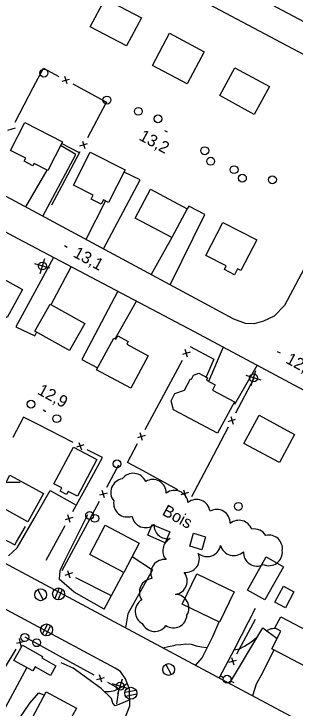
# Model space of a CAD drawing. Extents: x 219136 to 222520, y 5421589 to 5424530.
# Drawn here: x 220808.4 to 220879.7, y 5423742.7 to 5423918.8 of the extents above; entities that cross this region are included whole.
import ezdxf

# ---------------------------------------------------------------- set-up
doc = ezdxf.new("R2010")
doc.units = 0
for name, color, linetype in [('Level 19', 7, 'Continuous'), ('Level 2', 7, 'Continuous'), ('Level 21', 7, 'Continuous'), ('Level 3', 7, 'Continuous'), ('Level 31', 7, 'Continuous'), ('Level 36', 7, 'Continuous'), ('Level 37', 7, 'Continuous'), ('Level 44', 7, 'Continuous'), ('Level 61', 7, 'Continuous')]:
    doc.layers.add(name, color=color, linetype=linetype)

msp = doc.modelspace()

# ---------------------------------------------------------------- linework, layer by layer
at = {"layer": 'Level 19'}
for points in [[(220815.71, 5423867.5), (220824.08, 5423883.14), (220820.21, 5423885.48)], [(220816.77, 5423879.22), (220811.33, 5423869.85)], [(220831.13, 5423859.2), (220840.37, 5423876.71), (220836.32, 5423878.71)], [(220831.61, 5423871.39), (220826.62, 5423861.63)], [(220847.99, 5423850.13), (220856.79, 5423867.98), (220852.77, 5423870.05), (220852.29, 5423869.41)], [(220848.4, 5423862.1), (220843.18, 5423852.72)], [(220818.44, 5423857.04), (220808.89, 5423839.47), (220813.68, 5423837.13), (220814.16, 5423838.04)], [(220817.84, 5423845.07), (220822.89, 5423854.7)], [(220834.72, 5423848.47), (220825.61, 5423831.11), (220829.63, 5423829.05)], [(220834.08, 5423836.38), (220839.45, 5423845.98)], [(220861.48, 5423834.31), (220857.76, 5423825.6)], [(220870.07, 5423829.71), (220870.07, 5423829.7), (220864.33, 5423819.76)], [(220807.06, 5423781.33), (220809.21, 5423783.37), (220813.55, 5423790.78), (220817.55, 5423797.92), (220823.91, 5423794.35)], [(220827.05, 5423791.73), (220821.11, 5423779.89), (220820.05, 5423777.53), (220819.88, 5423775.43)], [(220838.39, 5423781.17), (220843.56, 5423777.78), (220837.27, 5423766.61), (220836.69, 5423763.04)], [(220831.25, 5423767.8), (220836.29, 5423777.13)], [(220869.61, 5423767.94), (220864.24, 5423757.54), (220860.43, 5423750.33)], [(220854.42, 5423753.54), (220856.1, 5423755.43), (220858.86, 5423760.84), (220860.44, 5423764.57)], [(220863.09, 5423748.9), (220871.52, 5423763.09), (220875.13, 5423760.38)], [(220874.34, 5423757.46), (220871.43, 5423751.64), (220869.79, 5423748.75), (220868.93, 5423745.78)], [(220837.77, 5423744.76), (220837.76, 5423744.76), (220835.39, 5423743.76), (220834.1, 5423743.26), (220833.5, 5423743.9), (220833.12, 5423745.1), (220830.54, 5423747.69), (220823.43, 5423752.81), (220820.34, 5423754.17)], [(220811.71, 5423752.96), (220805.01, 5423740.58), (220808.49, 5423738.12), (220812.45, 5423743.9), (220814.7, 5423746.55), (220816.11, 5423745.96)]]:
    msp.add_lwpolyline(points, dxfattribs=at)
at = {"layer": 'Level 2'}
for points in [[(220872.49, 5423762.36), (220873.63, 5423762.88), (220873.95, 5423762.92), (220874.72, 5423762.97)], [(220864.22, 5423757.5), (220865.64, 5423757.76), (220866.88, 5423758.4), (220868.19, 5423759.25), (220869.2, 5423760.02), (220870.18, 5423760.84)], [(220846.16, 5423757.97), (220847.63, 5423758.31), (220848.93, 5423758.58), (220849.45, 5423758.71), (220850.75, 5423758.86), (220852, 5423759.01), (220853.36, 5423758.89), (220854.6, 5423758.5), (220855.94, 5423758.26), (220857.44, 5423758.06)], [(220831.31, 5423746.92), (220832.64, 5423746.9), (220833.97, 5423747.16), (220835.21, 5423747.76), (220836.49, 5423748.52), (220837.08, 5423749.02)]]:
    msp.add_lwpolyline(points, dxfattribs=at)
at = {"layer": 'Level 21'}
for points in [[(220826.69, 5423937.93), (220900.24, 5423898.82), (220901.06, 5423896.99), (220901.36, 5423894.2), (220900.6, 5423891.33), (220898.93, 5423887.11), (220896.32, 5423881.44), (220893.83, 5423876.24), (220890.47, 5423870.14)], [(220995.49, 5423678.29), (220996.19, 5423681.93), (221004.73, 5423697.94), (221021.75, 5423729.83), (221039.74, 5423765.29), (221053.95, 5423791.88), (221056.68, 5423797.99), (221058, 5423802.9), (221058.22, 5423809.79), (221057.3, 5423814.77), (221055.3, 5423819.73), (221052.73, 5423823.47), (221048.19, 5423828.12), (221044.49, 5423830.59), (221027, 5423839.69), (220987.65, 5423860.46), (220947.14, 5423882.17), (220909.34, 5423902.28), (220864.28, 5423926.29)], [(220890.47, 5423870.14), (220876.98, 5423844.81), (220874.43, 5423842.18), (220871.7, 5423840.84), (220869.29, 5423840.24), (220867.08, 5423840.27), (220864.19, 5423841.41), (220808.77, 5423871.23), (220757.05, 5423898.78), (220743.22, 5423906.76), (220739.01, 5423909.89), (220736.41, 5423913.05), (220734.33, 5423917.05), (220733.8, 5423922.07)], [(220724.64, 5423919.94), (220726.19, 5423914.33), (220728.49, 5423909.82), (220732.21, 5423905.23), (220736.01, 5423901.71), (220742.64, 5423897.61), (220763.85, 5423886.35), (220809.37, 5423861.82), (220854.1, 5423838.27), (220902.48, 5423812.33), (220943.93, 5423790.02), (220983.67, 5423769), (221016, 5423751.84), (221018.21, 5423749.94), (221019.51, 5423747.38), (221019.63, 5423744.57), (221018.36, 5423740.94), (221004.35, 5423715.58), (220996.36, 5423700.59), (220991.52, 5423693.41), (220988.5, 5423688.97), (220985.79, 5423686.18), (220984.37, 5423685.17), (220983.05, 5423684.44)], [(220948.95, 5423703), (220904.47, 5423726.78), (220853.86, 5423753.84), (220802.2, 5423781.53), (220756.87, 5423805.98), (220752.54, 5423808.02), (220749.08, 5423809.42), (220742.93, 5423811.71), (220736.7, 5423813.64), (220729.21, 5423815.61), (220722.71, 5423817.16), (220715.9, 5423818.25), (220709.13, 5423819.02), (220700.46, 5423819.59), (220693.39, 5423819.74), (220687.57, 5423819.54), (220678.98, 5423818.61), (220672.46, 5423817.66), (220660.87, 5423814.84)], [(220837.82, 5423743.23), (220837.67, 5423747.47), (220836.68, 5423750.08), (220835.42, 5423751.94), (220834.1, 5423752.79), (220790.53, 5423776.18), (220757.42, 5423793.74), (220751.89, 5423796.6), (220745.6, 5423799.45), (220739.31, 5423801.83), (220731.18, 5423804.33), (220723.66, 5423806.27), (220711.25, 5423808.22), (220700.8, 5423809.13), (220692.45, 5423809.16), (220680.51, 5423808.54), (220669.68, 5423806.84), (220660.39, 5423804.75)], [(220831.25, 5423767.8), (220823.63, 5423772.14), (220819.88, 5423775.43)], [(220810.43, 5423694.93), (220812.84, 5423696.76), (220815.62, 5423700.25), (220820.54, 5423708.61), (220834.15, 5423733.92), (220837.82, 5423743.23)]]:
    msp.add_lwpolyline(points, dxfattribs=at)
at = {"layer": 'Level 3'}
for p, q in [((220846.58, 5423889.26), (220847.28, 5423888.88)), ((220821.23, 5423860.05), (220821.93, 5423859.67)), ((220875.19, 5423833.21), (220875.89, 5423832.83)), ((220815.82, 5423818.35), (220816.52, 5423817.97))]:
    msp.add_line(p, q, dxfattribs=at)
at = {"layer": 'Level 31'}
for points in [[(220836.98, 5423910.7), (220827.75, 5423915.56), (220831.54, 5423922.75), (220840.77, 5423917.88)], [(220852.31, 5423901.07), (220843.5, 5423905.77), (220847.85, 5423913.92), (220856.66, 5423909.23)], [(220869.33, 5423893.34), (220860.6, 5423898.1), (220864.45, 5423905.17), (220873.19, 5423900.41)], [(220811.17, 5423891.28), (220820.69, 5423886.41), (220816.96, 5423879.12), (220813.5, 5423880.89), (220813.21, 5423880.32), (220810.99, 5423881.46), (220811.4, 5423882.25), (220807.55, 5423884.22)], [(220827.75, 5423883.75), (220836.59, 5423879.24), (220832.39, 5423870.99), (220831.07, 5423871.66), (220830.5, 5423870.56), (220827.97, 5423871.85), (220828.47, 5423872.84), (220823.49, 5423875.38)], [(220843.03, 5423874.35), (220852.29, 5423869.41), (220848.4, 5423862.1), (220839.14, 5423867.04)], [(220861.37, 5423865.95), (220869.97, 5423861.53), (220865.96, 5423853.73), (220865.13, 5423854.16), (220864.34, 5423852.63), (220861.76, 5423853.96), (220862.24, 5423854.9), (220857.06, 5423857.56)], [(220806.65, 5423841.82), (220797.68, 5423846.8), (220801.59, 5423853.85), (220810.56, 5423848.88)], [(220822.5, 5423833.39), (220813.69, 5423838.3), (220817.55, 5423845.23), (220826.37, 5423840.32)], [(220838, 5423823.84), (220829.34, 5423828.51), (220833.69, 5423836.59), (220834.28, 5423836.27), (220834.74, 5423837.12), (220837.38, 5423835.69), (220837.02, 5423835.04), (220842.45, 5423832.11)], [(220860.05, 5423812.45), (220848.9, 5423818.39), (220848.23, 5423820.68), (220849.2, 5423822.5), (220851.66, 5423823.36), (220853.2, 5423826.26), (220853.39, 5423826.16), (220853.94, 5423827.2), (220855.26, 5423827.71), (220857.51, 5423826.51), (220857.19, 5423825.9), (220859.46, 5423824.7), (220858.76, 5423823.39), (220864.3, 5423820.44)], [(220875.71, 5423805), (220866.71, 5423809.86), (220870.55, 5423816.98), (220879.55, 5423812.13)], [(220818.55, 5423799.63), (220823.47, 5423808.92), (220829.42, 5423805.77), (220824.49, 5423796.46), (220822.18, 5423797.68), (220821.76, 5423796.89), (220820.13, 5423797.76), (220820.55, 5423798.57)], [(220811.96, 5423789.98), (220803.48, 5423794.58), (220807.38, 5423801.77), (220815.86, 5423797.18)], [(220831.54, 5423789.08), (220840.17, 5423784.57), (220836.29, 5423777.13), (220827.66, 5423781.64)], [(220843.46, 5423789.26), (220847.93, 5423787.38), (220846.79, 5423784.66), (220842.32, 5423786.53)], [(220852.98, 5423783.77), (220853.95, 5423787.08), (220856.98, 5423786.19), (220856.01, 5423782.88)], [(220867.61, 5423772.62), (220872.35, 5423781.07), (220876.79, 5423778.57), (220872.04, 5423770.13)], [(220860.53, 5423764.53), (220851.05, 5423769.09), (220854.74, 5423776.76), (220864.22, 5423772.2)], [(220874.59, 5423769.59), (220876.73, 5423773.61), (220879.4, 5423772.2), (220877.27, 5423768.17)], [(220876.07, 5423765.86), (220888.15, 5423759.54), (220884.32, 5423752.23), (220873.76, 5423757.76), (220876.11, 5423762.25), (220874.59, 5423763.04)], [(220813.19, 5423752.13), (220808.41, 5423754.8), (220810.55, 5423758.62), (220815.67, 5423755.75), (220815.5, 5423755.45), (220819.06, 5423753.45), (220817.66, 5423750.96), (220813.76, 5423753.15)], [(220811.64, 5423737.61), (220816.55, 5423746.78), (220824.24, 5423742.67), (220822.43, 5423739.29), (220822.85, 5423739.06), (220819.75, 5423733.27)]]:
    msp.add_lwpolyline(points, close=True, dxfattribs=at)
at = {"layer": 'Level 36'}
for p, q in [((220817.53, 5423854.29), (220813.72, 5423855.46)), ((220815.04, 5423852.97), (220816.21, 5423856.78)), ((220868.57, 5423824.56), (220869.74, 5423828.37)), ((220871.06, 5423825.88), (220867.25, 5423827.05)), ((220815.88, 5423770.11), (220814.48, 5423772.77)), ((220819.84, 5423773.17), (220818.74, 5423770.48)), ((220819.6, 5423770.15), (220820.7, 5423772.84)), ((220816.91, 5423764.01), (220815.58, 5423761.43)), ((220816.41, 5423761.03), (220817.74, 5423763.61)), ((220848.34, 5423751.14), (220846.94, 5423753.8)), ((220834.74, 5423746.32), (220835.91, 5423750.13)), ((220860.67, 5423750.96), (220861.55, 5423750.49)), ((220864.21, 5423749.1), (220863.31, 5423749.55)), ((220837.23, 5423747.64), (220833.42, 5423748.81)), ((220839.35, 5423747.19), (220836.51, 5423746.63)), ((220836.71, 5423745.73), (220839.55, 5423746.29))]:
    msp.add_line(p, q, dxfattribs=at)
for centre, radius in [((220816, 5423903.83), 1), ((220831.97, 5423896.98), 1), ((220839.94, 5423894.12), 1), ((220844.93, 5423892.22), 1), ((220856.79, 5423884.12), 1), ((220858.28, 5423881.46), 1), ((220864.23, 5423879.31), 1), ((220866.33, 5423877.16), 1), ((220873.95, 5423876.75), 1), ((220815.63, 5423854.88), 1), ((220869.16, 5423826.47), 1), ((220812.72, 5423819.82), 1), ((220819.25, 5423816.14), 1), ((220834.53, 5423804.68), 1), ((220865.31, 5423793.87), 1), ((220827.59, 5423791.57), 1), ((220828.9, 5423790.84), 1), ((220815.17, 5423771.45), 1.5), ((220819.71, 5423771.66), 1.52), ((220816.67, 5423762.52), 1.52), ((220811.17, 5423760.63), 1), ((220814.17, 5423759.28), 1), ((220847.63, 5423752.48), 1.5), ((220862.44, 5423750.02), 1), ((220835.33, 5423748.23), 1), ((220838.04, 5423746.46), 1.52)]:
    msp.add_circle(centre, radius, dxfattribs=at)
at = {"layer": 'Level 37'}
for p, q in [((220821.86, 5423901.08), (220821.29, 5423903)), ((220820.61, 5423901.75), (220822.53, 5423902.32)), ((220808.69, 5423889.86), (220806.78, 5423889.27)), ((220825.14, 5423885.34), (220827.05, 5423885.93)), ((220825.8, 5423886.59), (220826.39, 5423884.68)), ((220853.07, 5423832.98), (220851.15, 5423832.41)), ((220852.4, 5423831.74), (220851.83, 5423833.66)), ((220863.37, 5423816.69), (220863.96, 5423814.77)), ((220862.71, 5423815.43), (220864.62, 5423816.03)), ((220841.66, 5423811.87), (220839.74, 5423811.3)), ((220840.98, 5423810.63), (220840.41, 5423812.55)), ((220826.14, 5423809.48), (220824.24, 5423808.86)), ((220824.88, 5423810.12), (220825.5, 5423808.22)), ((220832, 5423797.26), (220830.08, 5423796.68)), ((220831.33, 5423796.01), (220830.75, 5423797.93)), ((220852.66, 5423797.39), (220850.74, 5423796.83)), ((220851.42, 5423798.07), (220851.98, 5423796.15)), ((220823.31, 5423791.06), (220821.38, 5423790.5)), ((220822.63, 5423789.82), (220822.07, 5423791.75)), ((220823.25, 5423776.98), (220821.34, 5423776.36)), ((220821.99, 5423777.62), (220822.6, 5423775.72)), ((220810.25, 5423758.36), (220809.78, 5423760.31)), ((220810.98, 5423759.57), (220809.04, 5423759.1)), ((220862.92, 5423754.32), (220864.84, 5423754.89)), ((220863.59, 5423755.56), (220864.16, 5423753.64)), ((220829.44, 5423749.93), (220831.36, 5423750.49)), ((220830.68, 5423749.25), (220830.12, 5423751.17))]:
    msp.add_line(p, q, dxfattribs=at)
for points in [[(220813.31, 5423900.19), (220815.89, 5423905.1), (220819.81, 5423902.99)], [(220823.33, 5423901.09), (220831.88, 5423896.48), (220831.74, 5423896.22)], [(220808.67, 5423891.34), (220813.31, 5423900.19)], [(220831.74, 5423896.22), (220827.04, 5423887.4)], [(220825.01, 5423883.59), (220820.46, 5423885.96)], [(220825.15, 5423883.87), (220820.45, 5423875.05)], [(220820.45, 5423875.05), (220817.91, 5423870.29)], [(220853.08, 5423834.42), (220859.1, 5423831.21), (220857.82, 5423828.3)], [(220846.4, 5423822.14), (220851.16, 5423830.94)], [(220857.82, 5423828.3), (220857.12, 5423826.72)], [(220869.25, 5423826.35), (220864.6, 5423817.5)], [(220841.65, 5423813.35), (220846.4, 5423822.14)], [(220814.52, 5423814.66), (220810.84, 5423816.55), (220808.1, 5423811.36)], [(220823.41, 5423810.09), (220814.52, 5423814.66)], [(220862.73, 5423813.96), (220858.08, 5423805.11)], [(220841.17, 5423802.86), (220837.16, 5423805.05), (220839.74, 5423809.83)], [(220828.11, 5423801.31), (220830.83, 5423806.27), (220826.97, 5423808.26)], [(220831.99, 5423798.73), (220835.04, 5423804.39)], [(220858.08, 5423805.11), (220853.43, 5423796.26)], [(220849.95, 5423798.07), (220841.17, 5423802.86)], [(220823.31, 5423792.54), (220828.11, 5423801.31)], [(220825.35, 5423786.41), (220830.09, 5423795.21)], [(220800.52, 5423788.31), (220808.59, 5423784.1), (220809.05, 5423784.88)], [(220809.05, 5423784.88), (220811.33, 5423788.77)], [(220816.58, 5423780.26), (220821.38, 5423789.03)], [(220820.6, 5423777.61), (220825.35, 5423786.41)], [(220832.99, 5423771.23), (220824.08, 5423775.77)], [(220869.6, 5423765.15), (220864.83, 5423756.36)], [(220811.12, 5423760.8), (220819.88, 5423755.99)], [(220803.76, 5423749.09), (220808.97, 5423757.63)], [(220819.88, 5423755.99), (220828.64, 5423751.17)], [(220832.15, 5423749.25), (220834.97, 5423747.7), (220834.44, 5423743.76)]]:
    msp.add_lwpolyline(points, dxfattribs=at)
at = {"layer": 'Level 44'}
for centre, start, end in [((220836.41, 5423797.44), 99.2697, 219.2697), ((220838.65, 5423798.81), 23.8435, 143.8435), ((220843.58, 5423797.23), 0.6178, 120.6178), ((220849.1, 5423794.48), 6.4843, 126.4843), ((220854.7, 5423792.16), 8.4454, 128.4454), ((220837.14, 5423794.64), 169.946, 289.946), ((220859.8, 5423789.64), 358.9297, 118.9297), ((220841.74, 5423791.95), 189.3845, 309.3845), ((220865.44, 5423786.88), 20.2823, 128.9668), ((220847.39, 5423789.11), 177.2625, 280.2978), ((220869.34, 5423784.68), 32.0536, 100.8346), ((220873.03, 5423783.14), 352.346, 102.4713), ((220849.6, 5423782.62), 117.2625, 220.2978), ((220857.4, 5423784.58), 229.4568, 349.4568), ((220864.16, 5423784.83), 194.7441, 314.7441), ((220851.97, 5423780.57), 263.3989, 23.3989), ((220870.06, 5423782.19), 177.0723, 297.0723), ((220873.02, 5423782.28), 246.4638, 6.4638), ((220846.57, 5423776.94), 83.5193, 203.5193), ((220848.87, 5423774.97), 278.6123, 38.6123), ((220843.66, 5423772.1), 94.5423, 214.5423), ((220849.32, 5423768.08), 328.928, 88.928), ((220842.61, 5423767.18), 121.3326, 241.3326), ((220848.83, 5423766.5), 236.6537, 356.6537), ((220844.09, 5423765.6), 204.8907, 324.8907)]:
    msp.add_arc(centre, 3.46, start, end, dxfattribs=at)
at = {"layer": 'Level 61'}
msp.add_lwpolyline([(220790, 5423800), (220800, 5423800), (220810, 5423800)], dxfattribs=at)

# ---------------------------------------------------------------- texts
at = {"layer": 'Level 3'}
for s, p in [('13,2', (220839.89, 5423887.01)), ('13,1', (220823.19, 5423857.34)), ('12,7', (220877.1, 5423830.4)), ('12,9', (220814.14, 5423822.51))]:
    msp.add_text(s, height=3, rotation=331.383, dxfattribs=at).set_placement(p)
at = {"layer": 'Level 44'}
msp.add_text('Bois', height=3, rotation=331.3547, dxfattribs=at).set_placement((220845.76, 5423791.84))

doc.saveas('drawing.dxf')
